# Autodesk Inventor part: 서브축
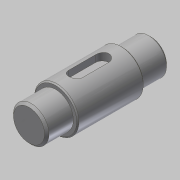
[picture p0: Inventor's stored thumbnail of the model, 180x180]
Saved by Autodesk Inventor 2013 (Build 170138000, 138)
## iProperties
Created: 2019-03
Part Number: 서브축
Material: 강철, 연강
Document SubType Name: Modeling
Designer: mduedu
Density: 1 g/cm^3
Author: mduedu
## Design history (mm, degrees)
sketch "스케치1"
  geometry: L1 (0, 0)-(12, 0); L2 (12, 0)-(12, 8); L3 (12, 8)-(0, 8); L4 (0, 8)-(0, 0); L5 (12, 0)-(42, 0); L6 (42, 0)-(42, 10); L7 (42, 10)-(12, 10); L8 (12, 10)-(12, 0); L9 (42, 0)-(55, 0); L10 (55, 0)-(55, 8); L11 (55, 8)-(42, 8); L12 (42, 8)-(42, 0)
  constraints: 24 end point, 6 parallel, 3 horizontal, 3 perpendicular
  dimensions: "d0" = 16 diameter of L3 L1; "d2" = 20 diameter of L7 L5; "d3" = 16 diameter of L11 L9; "d4" = 12 distance of L2.end L3.end; "d5" = 30 distance of L6.end L7.end; "d6" = 55 distance between parallel lines of L10 L4
revolve "회전1" sketch "스케치1" stored, may be unused: angle "d7" = 90 deg
node "작업 평면1"
sketch "스케치2" dims "d10" = 18
  geometry: L1 (6, -3)-(-6, -3); L2 (-6, -3)-(-6, 3); L3 (-6, 3)-(6, 3); L4 (6, 3)-(6, -3); L5 (15, 10)-(15, -10) reference; 3 further points
  constraints: 8 end point, 2 midpoint, 2 parallel, 2 vertical alignment, 1 horizontal, 1 horizontal alignment, 1 perpendicular, 4 other
  dimensions: "d8" = 6 distance between parallel lines of L3 L1; "d11" = 6 dimension on L5
extrude "돌출1" cut sketch "스케치2" distance "d12" = 3.5; taper "d13" = 0 deg
chamfer "모따기1" distance "d14" = 1; stored, may be unused: second distance "d15" = 2, angle "d16" = 45 deg
chamfer "모따기2" distance "d17" = 0.5; stored, may be unused: second distance "d18" = 2, angle "d19" = 45 deg
node "솔리드1"
